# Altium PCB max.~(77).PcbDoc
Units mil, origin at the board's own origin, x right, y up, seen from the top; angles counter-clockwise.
Board outline 2401.57 x 1653.54 mil, 2 copper layers (Top Layer, Bottom Layer); 13 components, 20 nets, 107 pads, 27 vias.
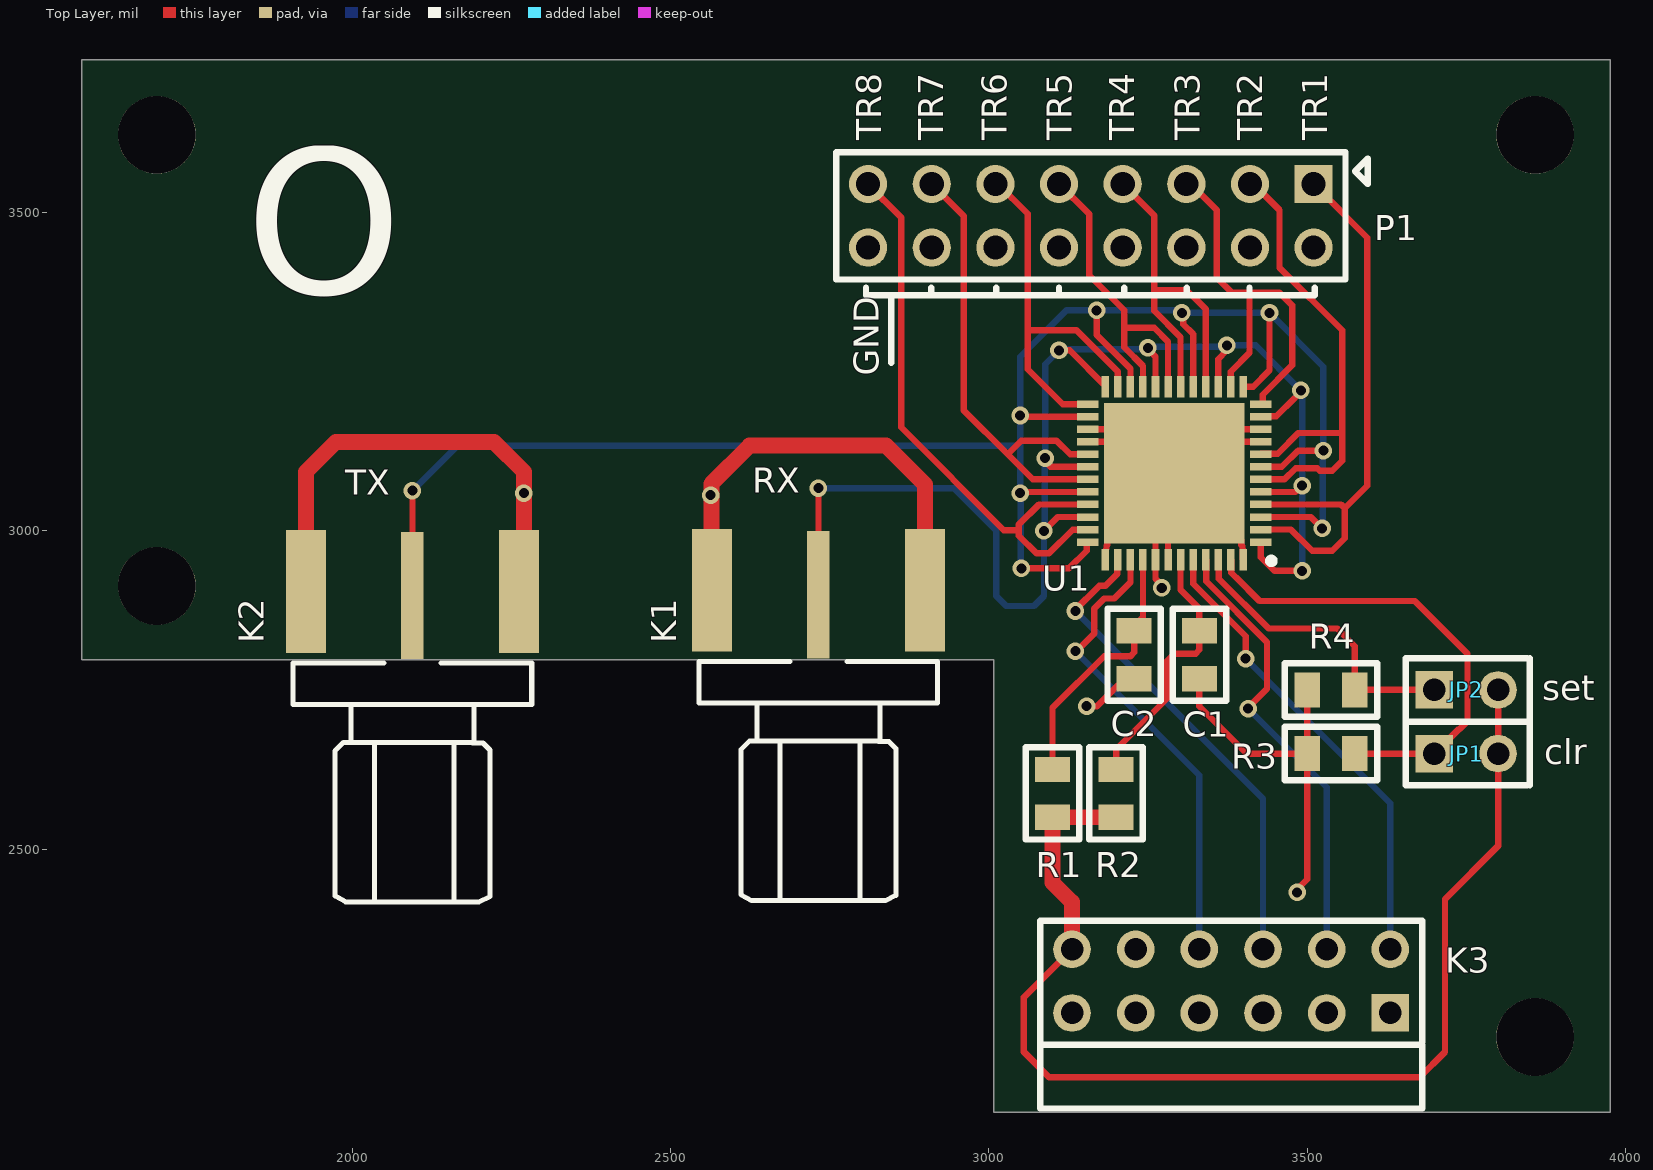
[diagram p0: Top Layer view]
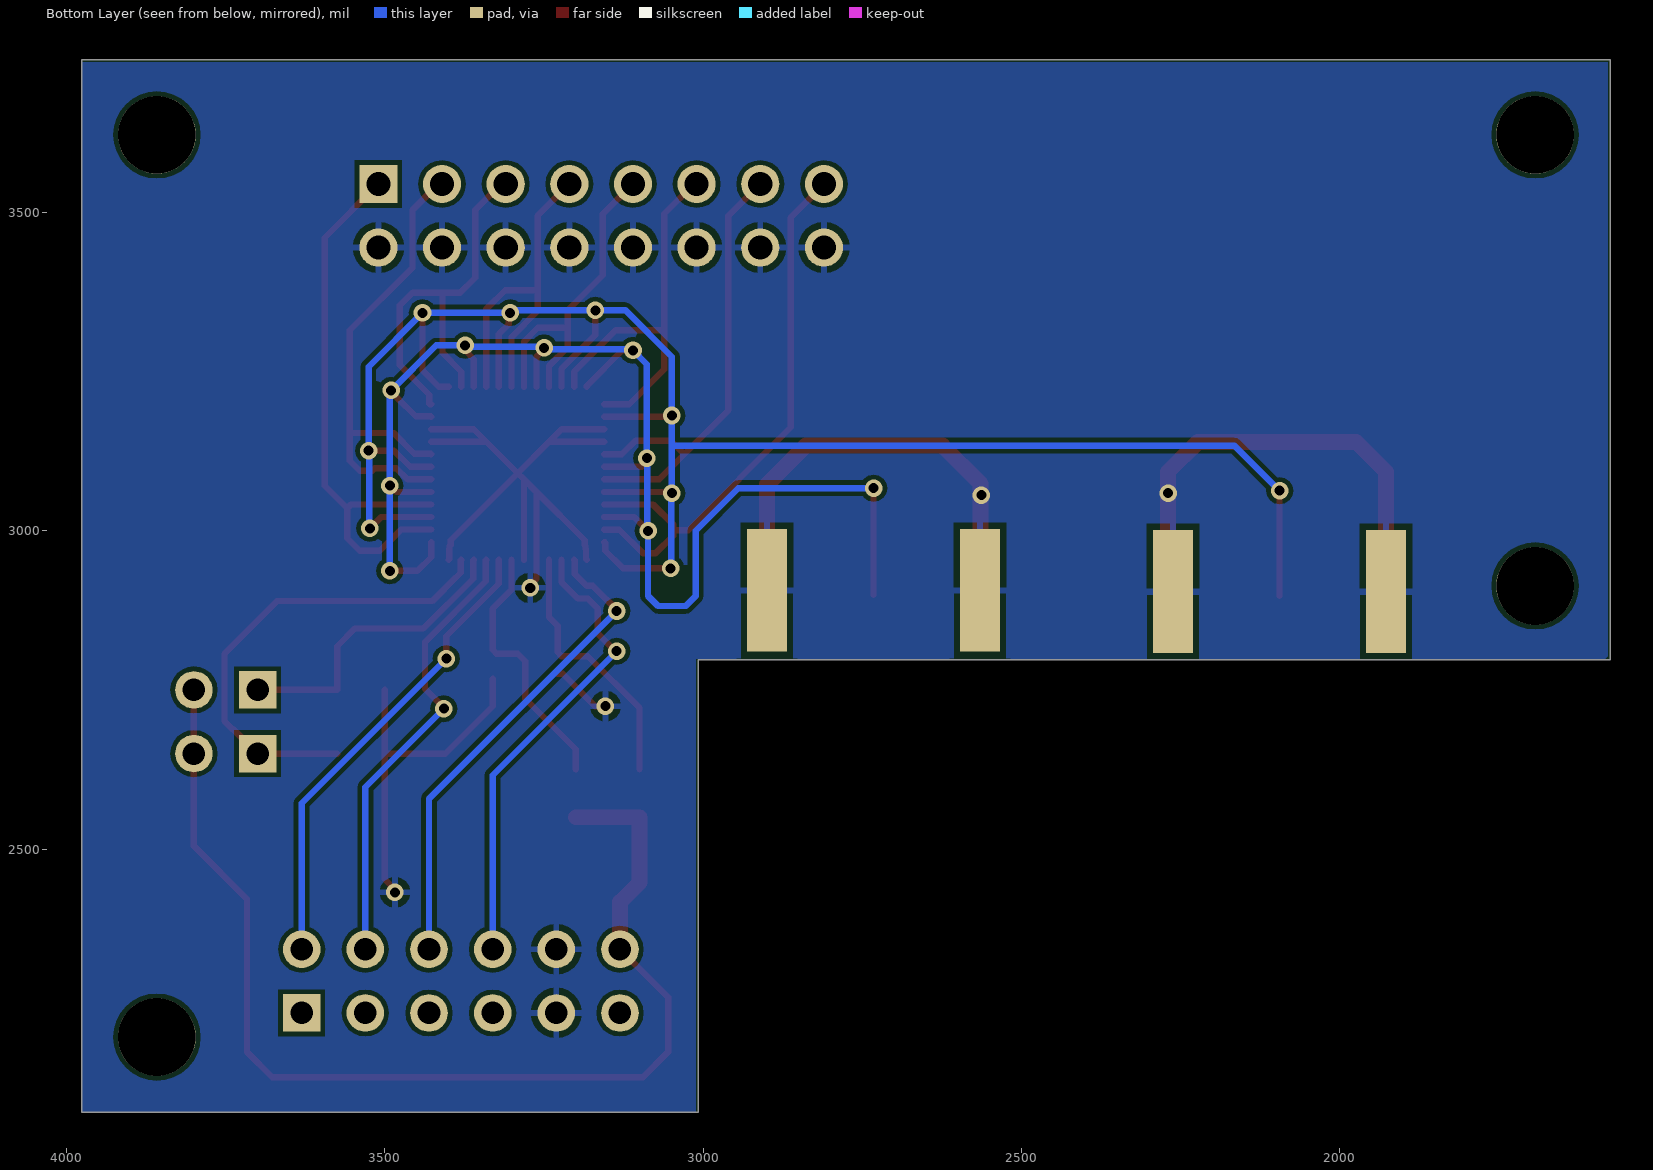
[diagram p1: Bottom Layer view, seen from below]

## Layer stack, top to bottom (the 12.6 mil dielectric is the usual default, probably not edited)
Top Solder: solder mask 0.4, Solder Resist, Dk 3.5
Top Layer: signal copper 1.4
Dielectric 1: dielectric 12.6, FR-4, Dk 4.8
Bottom Layer: signal copper 1.4
Bottom Solder: solder mask 0.4, Solder Resist, Dk 3.5

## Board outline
3008.02,2797.38 3008.02,2086.61 3976.38,2086.61 3976.38,3740.16 1574.8,3740.16 1574.8,2797.38

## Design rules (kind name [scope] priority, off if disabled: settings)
Clearance [All] p1: gap=7 ignorepadtopadclearanceinfootprint=TRUE
ComponentClearance [All] p1: gap=0 collisioncheckmode=3 verticalgap=0 showdistances=FALSE
HoleSize [All] p1: absolutevalues=TRUE maxlimit=150 minlimit=1 maxpercent=80.000 minpercent=20.000
MinimumSolderMaskSliver [All] p1: minsoldermaskwidth=0
PolygonConnect [All] p1: connectstyle=Relief reliefconductorwidth=10 reliefentries=4 polygonreliefangle="90 Angle" airgapwidth=10
RoutingVias [All] p1: holewidth=11.81 width=27.56 viastyle="Through Hole" minholewidth=11.81 minwidth=27.56 maxholewidth=11.81 maxwidth=27.56
SilkToSilkClearance [All] p1: silktosilkclearance=6
SilkToSolderMaskClearance [IsPad] p1: minsilkscreentomaskgap=4 clearancetoexposedcopper=TRUE
SolderMaskExpansion [All] p1: expansion=4 istentingtop=FALSE
Width [All] p1: maxlimit=100 minlimit=10 preferedwidth=10
25 further rules are at their usual default settings.

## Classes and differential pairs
component class max14866: C1 C2 JP2 K1 K2 K3 P1 R1 R2 R4 U1

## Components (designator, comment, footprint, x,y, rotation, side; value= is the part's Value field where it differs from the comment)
C1 "cap0805" SM0805 3330.71,2842.72 r270 top value=0.1
C2 "cap0805" SM0805 3228.35,2842.72 r270 top value=0.1
JP1 "JUMPER2" JUMPER2 3700,2650 r90 top
JP2 "JUMPER2" JUMPER2 3700,2750 r90 top
K1 "SMA_MALE_with_NUT" AMPHENOL_MALE 2732.28,2844.49 r90 top
K2 "SMA_MALE_with_NUT" AMPHENOL_MALE 2094.49,2842.52 r90 top
K3 "PMOD_6x2_ra_male_mirrored" PMOD_6x2_RA_MALE_MIRRORED 3130.71,2342.52 r0 top
P1 "2x8, 2.54mm vertical" "2x8 pin 2.54mm" 3510.24,3544.88 r270 top
R1 "res0805_EU" SM0805 3100,2625 r270 top value=10
R2 "res0805_EU" SM0805 3200,2625 r270 top value=10
R3 "res0805_EU" SM0805 3575,2650 r180 top value=10k
R4 "res0805_EU" SM0805 3575,2750 r180 top value=10k
U1 "MAX14866UTM+" QFN50P700X700X80-49N 3291.34,3090.55 r180 top

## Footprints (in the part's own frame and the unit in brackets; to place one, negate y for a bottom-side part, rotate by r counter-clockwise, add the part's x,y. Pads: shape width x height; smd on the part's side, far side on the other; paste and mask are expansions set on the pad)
"2x8 pin 2.54mm" [mil] "2x8 pin 2.54mm"
  rect 60x60 hole 38: 1(0,0)
  round 60 hole 38: 2(100,0) 3(0,-100) 4(100,-100) 5(0,-200) 6(100,-200) 7(0,-300) 8(100,-300) 9(0,-400) 10(100,-400) 11(0,-500) 12(100,-500) 13(0,-600) 14(100,-600) 15(0,-700) 16(100,-700)
  silkscreen extent -50,-750 150,85
AMPHENOL_MALE [mm]
  rect 5.1x0.9 smd: 1(1.397,0)
  rect 4.9x1.6 smd: 2(1.575,4.25) 2(1.575,-4.25)
  rect 4.9x1.6 smd far side: 2(1.575,4.25) 2(1.575,-4.25)
  silkscreen extent -10.81,-4.76 -1.28,4.76, body extent -10.8,-4.76 3.48,4.76, height 4.08
JUMPER2 [mm]
  rect 1.5x1.5 hole 0.9: 1(0,0)
  round 1.5 hole 0.9: 2(0,-2.54)
  silkscreen extent -1.27,-3.81 1.27,1.14
PMOD_6x2_RA_MALE_MIRRORED [mm] "2.54 mm right angle 6x2 pins"
  rect 1.5x1.5 hole 0.9: 1(12.7,-2.54)
  round 1.5 hole 0.9: 2(10.16,-2.54) 3(7.62,-2.54) 4(5.08,-2.54) 5(2.54,-2.54) 6(0,-2.54) 7(12.7,0) 8(10.16,0) 9(7.62,0) 10(5.08,0) 11(2.54,0) 12(0,0)
  silkscreen extent -1.27,-6.35 13.97,1.14
QFN50P700X700X80-49N [mm]
  rect 0.85x0.3 smd: 1(-3.45,2.75) 2(-3.45,2.25) 3(-3.45,1.75) 4(-3.45,1.25) 5(-3.45,0.75) 6(-3.45,0.25) 7(-3.45,-0.25) 8(-3.45,-0.75) 9(-3.45,-1.25) 10(-3.45,-1.75) 11(-3.45,-2.25) 12(-3.45,-2.75) 25(3.45,-2.75) 26(3.45,-2.25) 27(3.45,-1.75) 28(3.45,-1.25) 29(3.45,-0.75) 30(3.45,-0.25) 31(3.45,0.25) 32(3.45,0.75) 33(3.45,1.25) 34(3.45,1.75) 35(3.45,2.25) 36(3.45,2.75)
  rect 0.3x0.85 smd: 13(-2.75,-3.45) 14(-2.25,-3.45) 15(-1.75,-3.45) 16(-1.25,-3.45) 17(-0.75,-3.45) 18(-0.25,-3.45) 19(0.25,-3.45) 20(0.75,-3.45) 21(1.25,-3.45) 22(1.75,-3.45) 23(2.25,-3.45) 24(2.75,-3.45) 37(2.75,3.45) 38(2.25,3.45) 39(1.75,3.45) 40(1.25,3.45) 41(0.75,3.45) 42(0.25,3.45) 43(-0.25,3.45) 44(-0.75,3.45) 45(-1.25,3.45) 46(-1.75,3.45) 47(-2.25,3.45) 48(-2.75,3.45)
  rect 5.6x5.6 smd: 49(0,0)
  silkscreen extent -4,3.38 -3.75,3.62, body extent -3.55,-3.55 3.55,3.55, height 0.8
SM0805 [mil]
  rect 40x55 smd: 1(0,0) 2(75,0)
  silkscreen extent -35,-42 110,42

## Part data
C1 C2: "Capacitor"
K3: "PMOD_6x2_right_angle"
P1: library part "2x8, 2.54mm, vertical", "Header, 16-Pin"
R1 R2 R3 R4: "Resistor"
U1: "Integrated Circuit", Manufacturer_Name="Maxim Integrated", Mouser Part Number=700-MAX14866UTM+

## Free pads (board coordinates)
  round 122.05 hole 122.05 unplated: 0(1692.91,2913.39) 0(1692.91,3622.05) 0(3858.27,2204.72) 0(3858.27,3622.05)

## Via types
v1: diameter 27.56, hole 15.75, Top Layer to Bottom Layer, 27 vias

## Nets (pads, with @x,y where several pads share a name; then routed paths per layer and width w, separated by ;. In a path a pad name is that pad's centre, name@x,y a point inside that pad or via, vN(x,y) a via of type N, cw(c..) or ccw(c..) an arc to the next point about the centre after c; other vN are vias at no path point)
+5V: JP1.2 JP2.2 K3.12 R1.2 R2.2 | length 1810.4
  Top Layer w10: K3.12 3055.12,2266.93 3055.12,2181.1 3094.49,2141.73 3677.17,2141.73 3716.54,2181.1 3716.54,2421.26 3800,2504.72 JP1.2 JP2.2
  Top Layer w25: K3.12 3130.71,2416.54 3100,2447.24 R1.2 R2.2
clk: K3.8 U1.45 | length 716.2
  Top Layer w10: U1.45 3341.46,2953.82 3341.46,2920.48 3437.01,2824.93 3437.01,2751.97 v1@3405.51,2720.47
  Bottom Layer w10: v1(3407.48,2720.47) 3530.71,2597.24 K3.8
clr: JP1.1 R3.1 U1.47 | length 749.2
  Top Layer w10: U1.47 3380.83,2953.82 3380.83,2933.9 3388.73,2925.99 3388.97,2925.99 3425.2,2889.76 3669.29,2889.76 3751.97,2807.09 3751.97,2700.79 3739.85,2688.67 3738.67,2688.67 JP1.1 3578.94,2650 R3.1
din: K3.7 U1.44 | length 734.5
  Top Layer w10: U1.44 3320.87,2917.03 3403.54,2834.35 3403.54,2807.32 3403.31,2807.09 v1@3401.57,2807.09
  Bottom Layer w10: v1(3403.54,2799.21) 3630.71,2572.05 K3.7
dout: K3.10 U1.39 | length 734.9
  Top Layer w10: v1@3137.8,2811.02 3165.35,2838.58 3165.35,2877.95 3181.1,2893.7 3196.85,2893.7 3222.44,2919.29 U1.39
  Bottom Layer w10: v1(3135.83,2811.02) 3330.71,2616.14 3330.71,2350.39 K3.10@3326.77,2346.46
GND: C1.2 C2.2 K1.2 K2.2 K3.5 K3.11 P1.2 P1.4 P1.6 P1.8 P1.10 P1.12 P1.14 P1.16 R3.2 R4.2 U1.9 U1.10 U1.27 U1.28 U1.37 U1.41 U1.42 U1.48 U1.49 | length 3288.5
  Top Layer w10: v1(3153.54,2724.41) 3169.86,2724.41 3220.85,2775.39 C2.2@3228.35,2775.39 ; U1.28 U1.49@3242.13,3139.76 ; U1.27 3222.44,3159.45 U1.49@3242.13,3139.76 ; U1.37 3183.98,2955.63 3183.98,2971.14 3184.85,2972.01 3184.85,2976.43 3186.1,2977.68 3186.1,2985.32 U1.49@3261.81,3061.02 ; v1(3271.65,2910.43) 3271.65,2914.56 3261.81,2924.4 U1.41 U1.49@3261.81,3061.02 ; U1.42 U1.49@3281.5,3080.71 ; C1.2 3330.71,2724.41 3405.12,2650 R3.2 ; U1.48 3398.7,2955.63 3398.7,2971.14 3398.43,2971.41 3398.43,2975.82 3396.57,2977.68 3396.57,2985.32 U1.49 ; U1.9 U1.49@3340.55,3139.76 ; U1.10 3360.24,3159.45 U1.49@3340.55,3139.76 ; v1(3484.25,2432.09) 3484.25,2436.84 3492.14,2444.73 3492.14,2444.9 3500,2452.76 R3.2 ; R4.2 R3.2 ; U1.49@3242.13,3139.76 U1.49 ; U1.49@3261.81,3061.02 U1.49@3281.5,3080.71 ; U1.49@3281.5,3080.71 U1.49 ; U1.49 U1.49@3340.55,3139.76
  Top Layer w25: K2.2@1927.17,2904.53 1927.17,3092.52 1974.41,3139.76 2222.44,3139.76 2269.68,3092.52 2269.68,2912.4 K2.2@2261.81,2904.53 ; K1.2@2564.96,2906.5 2563.98,2907.48 2563.98,3056.1 2563.98,3073.82 2624.02,3133.86 2838.58,3133.86 2899.61,3072.83 K1.2@2899.61,2906.5
  other v1: 2562.99,3056.1 2269.68,3059.06
le: K3.9 U1.38 | length 768.7
  Top Layer w10: v1@3133.86,2874.02 3173.23,2913.39 3183.07,2913.39 3201.85,2932.17 3201.85,2953.82 U1.38
  Bottom Layer w10: v1(3135.83,2874.02) 3430.71,2579.13 K3.9
NetC1_1: C1.1 R2.1 U1.43 | length 415.7
  Top Layer w10: R2.1 3200,2656.69 3279.53,2736.22 3279.53,2795.28 3291.34,2807.09 3324.85,2807.09 3330.71,2812.94 C1.1 3330.71,2877.95 3301.18,2907.48 U1.43
NetC2_1: C2.1 R1.1 U1.40 | length 412.8
  Top Layer w10: R1.1 3100,2722.05 3181.1,2803.15 3222.49,2803.15 3228.35,2809.01 3228.35,2850.39 3242.13,2864.17 U1.40
NetK1_1: K1.1 U1.1 U1.5 U1.11 U1.15 U1.20 U1.24 U1.30 U1.34 | length 2369.1
  Top Layer w10: K1.1 v1(2732.28,3066.93) ; v1(3086.61,3000) 3108.27,3021.65 U1.34 ; v1@3086.61,3110.24 3096.46,3100.39 U1.30 ; v1(3110.24,3283.46) 3127.05,3283.46 3183.07,3227.44 U1.24 ; v1@3251.97,3283.46 3261.81,3273.62 U1.20 ; U1.15 3360.24,3269.69 3374.02,3283.46 v1(3374.02,3291.34) ; U1.1 3427.17,2958.66 3448.82,2937.01 v1(3492.13,2937.01) ; U1.5 3481.47,3061.02 3491.31,3070.87 v1(3492.13,3070.87) ; U1.11 3428.07,3180.04 3451.69,3180.04 3480.32,3208.66
  Bottom Layer w10: v1(2732.28,3066.93) 2944.88,3066.93 3011.81,3000 3011.81,2897.64 3027.56,2881.89 3070.87,2881.89 3086.61,2897.64 v1(3086.61,3000) 3087.6,3000.98 3087.6,3113.19 v1(3088.58,3114.17) 3088.58,3261.81 v1(3110.24,3283.46) 3112.2,3285.43 3248.03,3285.43 v1(3250,3287.4) 3251.97,3289.37 3372.05,3289.37 v1(3374.02,3291.34) 3419.29,3291.34 v1(3490.16,3220.47) 3492.13,3218.5 v1(3492.13,3070.87) 3492.13,2981.71 v1(3492.13,2937.01)
NetK2_1: K2.1 U1.3 U1.7 U1.13 U1.17 U1.22 U1.26 U1.32 U1.36 | length 3242.2
  Top Layer w10: K2.1 v1(2094.49,3062.99) ; v1@3047.24,3059.06 3049.21,3061.02 U1.32 ; v1(3051.18,2940.94) 3125.98,2940.94 3153.54,2968.5 3153.54,2981.38 3154.45,2982.28 U1.36 ; v1@3051.18,3181.1 3053.15,3179.13 U1.26 ; v1(3169.29,3346.46) 3169.29,3307.61 3222.44,3254.46 U1.22 ; v1@3299.21,3338.58 3301.45,3338.58 3305.63,3334.41 3305.63,3324.3 3320.87,3309.05 U1.17 ; U1.13 3415.35,3226.38 3440.94,3251.97 v1(3440.94,3342.52) ; U1.3 3505.91,3021.65 v1(3523.62,3003.94) ; U1.7 3427.28,3100.51 3460.32,3100.51 3485.8,3125.98 v1@3523.62,3125.98
  Bottom Layer w10: v1(2094.49,3062.99) 2165.35,3133.86 3049.21,3133.86 ; v1(3051.18,2940.94) 3050.2,2941.93 3050.2,3058.07 v1(3049.21,3059.06) 3049.21,3133.86 ; v1(3523.62,3003.94) 3524.61,3004.92 3524.61,3125 v1(3525.59,3125.98) 3525.59,3257.87 v1(3440.94,3342.52) v1(3303.15,3342.52) 3298.4,3342.52 3294.46,3346.46 v1(3169.29,3346.46) 3122.05,3346.46 3049.21,3273.62 v1(3049.21,3181.1) 3049.21,3133.86
set: JP2.1 R4.1 U1.46 | length 481.8
  Top Layer w10: U1.46 3361.14,2953.82 3361.14,2924.84 3439.52,2846.46 3547.24,2846.46 3575,2818.7 R4.1 JP2.1
tr1: P1.1 U1.2 U1.4 | length 894.5
  Top Layer w10: U1.2 3474.41,3001.97 3507.87,2968.5 3539.37,2968.5 3559.06,2988.19 3559.06,3035.43 ; U1.4 3553.15,3041.34 3559.06,3035.43 ; P1.1 3594.49,3460.63 3594.49,3070.87 3559.06,3035.43
tr2: P1.3 U1.6 U1.8 | length 783.1
  Top Layer w10: P1.3 3415.75,3544.88 3456.69,3503.94 3456.69,3413.39 3555.12,3314.96 3555.12,3153.54 ; U1.6 3464.57,3080.71 3482.28,3098.43 3515.75,3098.43 3519.68,3094.49 3539.37,3094.49 3555.12,3110.24 3555.12,3153.54 ; U1.8 3428.07,3120.98 3453.66,3120.98 3486.22,3153.54 3555.12,3153.54
tr3: P1.5 U1.12 U1.14 | length 644.5
  Top Layer w10: P1.5 3317.32,3544.88 3358.27,3503.94 3358.27,3397.64 3381.89,3374.02 3409.45,3374.02 ; U1.14 3380.04,3226.49 3380.04,3250.11 3409.45,3279.53 3409.45,3374.02 ; U1.12 3429.5,3198.82 3430.4,3199.72 3430.4,3213.87 3476.38,3259.84 3476.38,3354.33 3456.69,3374.02 3409.45,3374.02
tr4: P1.7 U1.16 U1.18 | length 572.8
  Top Layer w10: P1.7 3259.84,3495.28 3259.84,3381.89 ; U1.18 3301.18,3304.13 3259.84,3345.47 3259.84,3377.95 3259.84,3381.89 ; U1.16 3340.55,3348.43 3311.02,3377.95 3263.78,3377.95 3259.84,3381.89
tr5: P1.9 U1.19 U1.21 | length 521.9
  Top Layer w10: P1.9 3157.48,3497.64 3157.48,3401.57 3212.6,3346.46 3212.6,3318.9 ; U1.21 3242.13,3258.82 3212.6,3288.35 3212.6,3318.9 ; U1.19 3281.5,3297.24 3259.84,3318.9 3212.6,3318.9
tr6: P1.11 U1.23 U1.25 | length 623.9
  Top Layer w10: P1.11 3014.17,3544.88 3061.02,3498.03 3061.02,3314.96 ; U1.25 3116.14,3198.82 3061.02,3253.94 3061.02,3314.96 ; U1.23 3202.43,3226.7 3202.43,3250.32 3137.8,3314.96 3061.02,3314.96
tr7: P1.13 U1.29 U1.31 | length 760.4
  Top Layer w10: P1.13 2960.63,3494.49 2960.63,3188.98 3029.53,3120.08 ; U1.31 3068.9,3080.71 3029.53,3120.08 ; U1.29 3127.95,3120.08 3106.3,3141.73 3051.18,3141.73 3029.53,3120.08
tr8: P1.15 U1.33 U1.35 | length 930.1
  Top Layer w10: P1.15 2810.24,3544.09 2862.2,3492.13 2862.2,3162.4 3023.62,3000.98 3047.24,3000.98 ; U1.35 3155.4,3001.85 3131.78,3001.85 3094.49,2964.57 3074.8,2964.57 3047.24,2992.13 3047.24,3000.98 ; U1.33 3078.74,3041.34 3047.24,3009.84 3047.24,3000.98
pads on no net: K3.1 K3.2 K3.3 K3.4 K3.6

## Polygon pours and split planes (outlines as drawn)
GND on Bottom Layer "GND_L02_P000" (solid, pour order 0): 1578.74,3736.22 1578.74,2803.15 1582.68,2799.21 3011.81,2799.21 3011.81,2086.61 3976.38,2086.61 3976.38,3736.22

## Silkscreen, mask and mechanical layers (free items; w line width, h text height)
Top Overlay:
  lines w10: 2807.09,3381.89 2807.09,3370.08 2846.46,3370.08 ; 2846.46,3263.78 2846.46,3370.08 ; 2909.45,3370.08 2909.45,3381.89 ; 3011.81,3370.08 3011.81,3381.89 ; 3110.24,3370.08 3110.24,3381.89 ; 3212.6,3370.08 3212.6,3381.89 ; 3311.02,3370.08 3311.02,3381.89 ; 3409.45,3370.08 3409.45,3381.89 ; 3511.81,3381.89 3511.81,3370.08 2846.46,3370.08
  text "TR8" at 2831.1,3613.78 h39.37 r90
  text "TR6" at 3027.95,3613.78 h39.37 r90
  text "TR5" at 3130.32,3613.78 h39.37 r90
  text "TR4" at 3228.74,3613.78 h39.37 r90
  text "TR3" at 3331.1,3613.78 h39.37 r90
  text "TR2" at 3429.53,3613.78 h39.37 r90
  text "TR1" at 3531.89,3613.78 h39.37 r90
  text "TR7" at 2928.47,3613.35 h39.37 r90
  text "O" at 1831.69,3260.83 h590.55
  text "GND" at 2827.17,3243.7 h39.37 r90
  text "RX" at 2628.54,3059.65 h39.37
  text "TX" at 1988.78,3056.69 h39.37
  text "set" at 3869.68,2733.86 h39.37
  text "clr" at 3872.64,2633.46 h39.37
Mechanical 1:
  lines w10: 1574.8,2795.28 3007.87,2795.28 3007.87,2086.61 3976.38,2086.61 3976.38,3740.16 1574.8,3740.16 1574.8,2795.28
